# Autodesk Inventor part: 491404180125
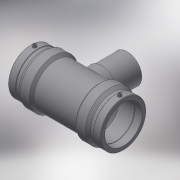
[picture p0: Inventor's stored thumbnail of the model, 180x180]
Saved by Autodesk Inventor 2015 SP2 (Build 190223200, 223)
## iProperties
Created: 2017-06
Part Number: 491404180125
Material: Generic
Description: PLASSON REDUCING TEE 180x125x180
Document SubType Name: Modeling
Designer: KIM
Mass: 7830 g
Surface Area: 6589.32 cm^2
Volume: 7830 cm^3
Density: 1 g/cm^3
Appearance: Default
Author: KIM
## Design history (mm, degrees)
derived "491404.ipt"
feature "Solid1::491404.ipt"
tag "TaggingFeature1"
body "Solid1"
other parameters: "d0" = 422, "d2" = 245, "d3" = 106, "d4" = 84.4, "d5" = 220.5, "d6" = 171, "d8" = 168 deg, "d10" = 42.4, "d11" = 14.13333, "d13" = 422, "d14" = 17.6296, "d17" = 162, "d19" = 3.52592, "d20" = 168 deg, "d22" = 227.85, "d23" = 245, "d25" = 135 deg, "d26" = 295.4, "d29" = 116, "d30" = 15, "d31" = 168.8, "d34" = 5 deg, "d35" = 15, "d39" = 5 deg, "d41" = 4, "d42" = 14, "d43" = 0, "d45" = 4, "d46" = 6, "d47" = 0, "d48" = -225, "d49" = 125, "d51" = 0, "d54" = 0, "d55" = 220.5, "d56" = 245, "d57" = 147.7, "d58" = 135 deg, "d59" = 106, "d60" = 106, "d61" = 135 deg, "d62" = 225, "d72" = 192.01, "d73" = 96.005, "d74" = -225, "d75" = 131.25, "d77" = 0, "d80" = 0, "d81" = 125, "d82" = 102.5, "d83" = 0, "d84" = 3, "d85" = 0, "d86" = 35.33333, "d87" = 223.293, "d88" = 14.13333, "d89" = 3, "d90" = 0, "L_" = 422, "L_1" = 106, "D_" = 245, "A_" = 116, "d_2" = 12, "H_" = 225, "d_1" = 125
